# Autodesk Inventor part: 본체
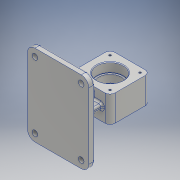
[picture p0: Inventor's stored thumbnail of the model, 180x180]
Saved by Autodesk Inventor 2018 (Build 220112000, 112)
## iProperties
Created: 2020-11
Part Number: 본체
Material: 알루미늄 6061
Document SubType Name: Modeling
Designer: 1class 3
Density: 2.7 g/cm^3
Appearance: 알루미늄 - 평지
Mass: 682.106 g
Surface Area: 541.326 cm^2
Volume: 252.632 cm^3
Author: 1class 3
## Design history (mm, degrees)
sketch "스케치1"
  geometry: L1 (-32, -32)-(32, -32); L2 (32, -32)-(32, 32); L3 (32, 32)-(-32, 32); L4 (-32, 32)-(-32, -32); L5 (-32, -32)-(32, 32); L6 (32, -32)-(-32, 32); 1 further point
  constraints: 12 end point, 2 midpoint, 2 parallel, 1 horizontal, 1 perpendicular
  dimensions: "d0" = 64 distance of L3.end L2.end; "d1" = 64 distance of L2.end L1.end
extrude "돌출1" new body sketch "스케치1" stored distance "d2" = 42; taper "d3" = 0 deg
fillet "모깎기1" dims "d4" = 8
sketch "스케치2"
  geometry: C1 r 18 at (0, 0); 1 further point
  constraints: 1 centre point, 1 coincident
  dimensions: "d5" = 36 diameter of C1
extrude "돌출2" cut sketch "스케치2" distance "d6" = 42; taper "d7" = 0 deg
sketch "스케치3"
  geometry: L1 (-24, 32)-(24, 32) reference; L2 (32, 24)-(32, -24) reference; L3 (24, -32)-(-24, -32) reference; L4 (-32, -24)-(-32, 24) reference; C1 r 21 at (0, 0); C2 r 18 at (0, 0) reference; A1 r 8 centre (-24, 24) between (-24, 32) and (-32, 24) reference; A2 r 8 centre (24, 24) between (32, 24) and (24, 32) reference; A3 r 8 centre (24, -24) between (24, -32) and (32, -24) reference; A4 r 8 centre (-24, -24) between (-32, -24) and (-24, -32) reference; 1 further point
  constraints: 1 centre point, 1 coincident
  dimensions: "d8" = 42 diameter of C1
extrude "돌출3" cut sketch "스케치3" distance "d9" = 15; taper "d10" = 0 deg
sketch "스케치4"
  geometry: L1 (32, 24)-(32, -24) reference; L2 (24, -32)-(-24, -32) reference; L3 (-32, -24)-(-32, 24) reference; L4 (-24, 32)-(24, 32) reference; C1 r 21 at (0, 0); C2 r 18 at (0, 0) reference; A1 r 8 centre (24, 24) between (32, 24) and (24, 32) reference; A2 r 8 centre (24, -24) between (24, -32) and (32, -24) reference; A3 r 8 centre (-24, -24) between (-32, -24) and (-24, -32) reference; A4 r 8 centre (-24, 24) between (-24, 32) and (-32, 24) reference; 1 further point
  constraints: 1 centre point, 1 coincident
  dimensions: "d11" = 42 diameter of C1
extrude "돌출4" cut sketch "스케치4" distance "d12" = 15; taper "d13" = 0 deg
fillet "모깎기2" dims "d14" = 0.3
chamfer "모따기1" distance "d15" = 1; stored, may be unused: second distance "d16" = 2, angle "d17" = 45 deg
sketch "스케치7"
  geometry: L1 (-24, -24)-(24, -24); L2 (24, -24)-(24, 24); L3 (24, 24)-(-24, 24); L4 (-24, 24)-(-24, -24); L5 (-24, -24)-(24, 24); L6 (24, -24)-(-24, 24); 5 further points
  constraints: 12 end point, 4 coincident, 2 midpoint, 2 parallel, 1 horizontal, 1 perpendicular
  dimensions: "d36" = 48 distance of L3.end L2.end; "d37" = 48 distance of L2.end L1.end
hole "구멍1" sketch "스케치7" at (-24, 24), (24, 24), (24, -24), (-24, -24) diameter "d38" = 3.242; stored, may be unused: countersink angle "d42" = 90 deg, drill point angle "d44" = 118 deg; dims "d39" = 8, "d40" = 4, "d41" = 2, "d43" = 10
node "작업 평면2"
sketch "스케치10"
  geometry: L1 (0, 0)-(62, 0); L2 (62, 0)-(62, -65); L3 (62, -65)-(0, -65); L4 (0, -65)-(0, 0); L5 (0, 0)-(62, 0); L6 (62, 0)-(62, 65); L7 (62, 65)-(0, 65); L8 (0, 65)-(0, 0); L9 (0, 65)-(-36, 65); L10 (-36, 65)-(-36, -65); L11 (-36, -65)-(0, -65); L12 (0, -65)-(0, 65)
  constraints: 24 end point, 6 parallel, 3 horizontal, 3 perpendicular
  dimensions: "d56" = 62 distance of L2.end L3.end; "d57" = 65 distance of L1.end L2.end; "d58" = 62 distance of L7.end L6.end; "d59" = 65 distance of L6.end L5.end; "d60" = 36 distance of L11.end L10.end; "d61" = 130 distance of L10.end L9.end
extrude "돌출8" join sketch "스케치10" distance "d62" = 10; taper "d63" = 0 deg
sketch "스케치11"
  geometry: L1 (20, -4)-(-20, -4); L2 (-20, -4)-(-20, 4); L3 (-20, 4)-(20, 4); L4 (20, 4)-(20, -4); L5 (20, -4)-(-20, 4); L6 (-20, -4)-(20, 4); L7 (4, -17)-(-4, -17); L8 (-4, -17)-(-4, 17); L9 (-4, 17)-(4, 17); L10 (4, 17)-(4, -17); L11 (4, -17)-(-4, 17); L12 (-4, -17)-(4, 17); 1 further point
  constraints: 24 end point, 4 midpoint, 4 parallel, 2 horizontal, 2 perpendicular
  dimensions: "d64" = 40 distance of L2.end L3.end; "d65" = 8 distance of L1.end L2.end; "d66" = 8 distance of L8.end L9.end; "d67" = 34 distance of L7.end L8.end
extrude "돌출9" join sketch "스케치11" stored distance "d68" = 10; taper "d69" = 0 deg
fillet "모깎기6" dims "d70" = 3
fillet "모깎기7" dims "d71" = 12
sketch "스케치12"
  geometry: C1 r 4.5 at (-50, -53); C2 r 4.5 at (-50, 53); C3 r 4.5 at (24, 53); C4 r 4.5 at (24, -53); A1 r 12 centre (-50, -53) between (-62, -53) and (-50, -65) reference; A2 r 12 centre (-50, 53) between (-50, 65) and (-62, 53) reference; A3 r 12 centre (24, 53) between (36, 53) and (24, 65) reference; A4 r 12 centre (24, -53) between (24, -65) and (36, -53) reference; 1 further point
  constraints: 4 centre point, 4 coincident
  dimensions: "d72" = 9 diameter of C1; "d73" = 9 diameter of C2; "d74" = 9 diameter of C3; "d75" = 9 diameter of C4
extrude "돌출10" cut sketch "스케치12" distance "d76" = 10; taper "d77" = 0 deg
fillet "모깎기8" dims "d78" = 3
sketch "스케치14"
  geometry: L1 (24, 65)-(-50, 65) reference; L2 (-62, 53)-(-62, -53) reference; 2 further points
  constraints: 1 other
  dimensions: "d83" = 65 distance from line of L1 point (-52, 0); "d84" = 10 distance from line of L2 point (-52, 0)
feature "엠보싱3" sketch "스케치14" dims "d85" = 0.5, "d86" = 0
node "솔리드1"
mirror "미러1"
node "절단 모서리 투영1"
node "절단 모서리 투영2"
